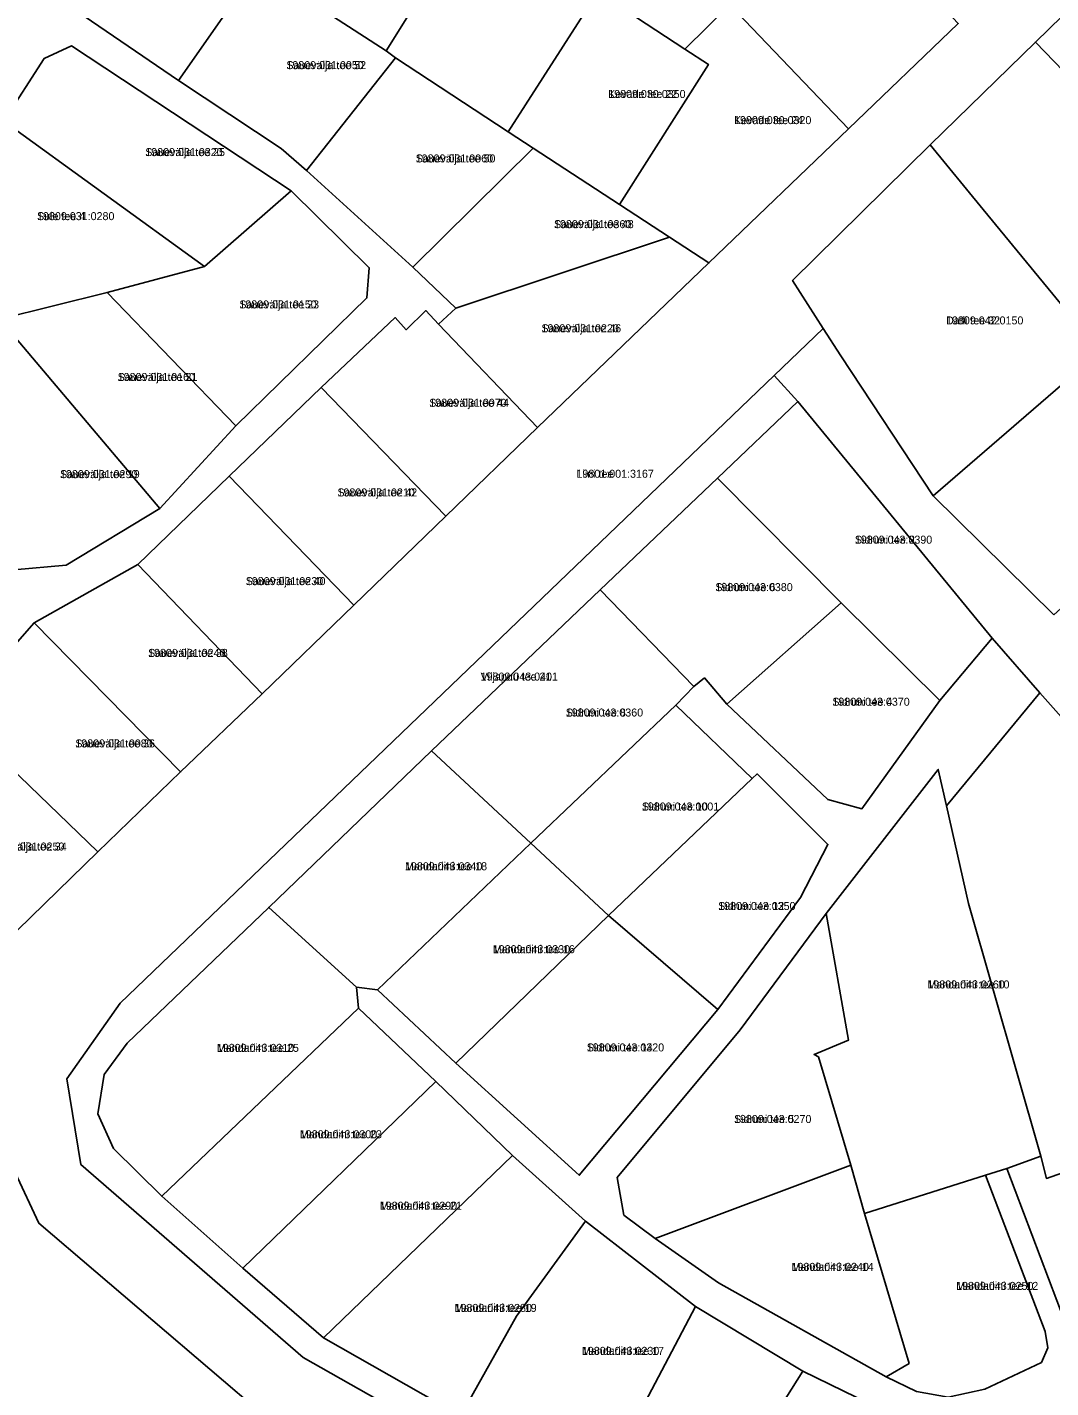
# Model space of a CAD drawing. Extents: x 516875 to 535633, y 6574491 to 6593094.
# Drawn here: x 521809.5 to 522001.4, y 6588394.7 to 6588649.8 of the extents above; entities that cross this region are included whole.
import ezdxf

# ---------------------------------------------------------------- set-up
doc = ezdxf.new("R2010")
doc.units = 0
for name, color, linetype in [('L_AADRESS', 7, 'Continuous'), ('PIIR', 7, 'Continuous'), ('TUNNUS', 7, 'Continuous')]:
    doc.layers.add(name, color=color, linetype=linetype)

msp = doc.modelspace()

# ---------------------------------------------------------------- linework, layer by layer
at = {"layer": 'PIIR'}
for points in [[(521893.2, 6588671.62), (521876.83, 6588645.41), (521853.89, 6588660.25), (521870.17, 6588686.73)], [(521814.85, 6588655.55), (521828.99, 6588676.38), (521833.01, 6588673.97), (521852.62, 6588660.96), (521837.89, 6588639.86)], [(521961.79, 6588674.13), (521984.07, 6588650.49), (521963.51, 6588630.77), (521941.24, 6588653.99)], [(521893.2, 6588671.62), (521916.51, 6588656.43), (521899.69, 6588630.21), (521878.54, 6588644.11), (521876.83, 6588645.41)], [(522009.11, 6588636.07), (521998.56, 6588647.03), (522021.19, 6588669.13), (522031.66, 6588658.42), (522052.99, 6588636.81), (522029.9, 6588614.7)], [(521837.89, 6588639.86), (521852.62, 6588660.96), (521853.89, 6588660.25), (521876.83, 6588645.41), (521878.54, 6588644.11), (521861.88, 6588622.95), (521857.12, 6588627.09)], [(521932.81, 6588645.73), (521937.22, 6588642.84), (521920.56, 6588616.58), (521904.35, 6588627.17), (521899.69, 6588630.21), (521916.51, 6588656.43)], [(521963.51, 6588630.77), (521937.33, 6588605.63), (521929.94, 6588610.46), (521920.56, 6588616.58), (521937.22, 6588642.84), (521932.81, 6588645.73), (521941.24, 6588653.99)], [(521812.66, 6588643.98), (521805.09, 6588632.22), (521787.69, 6588607.6), (521780.83, 6588600.74), (521749.9, 6588570.67), (521765.69, 6588556.88), (521780.6, 6588551.45), (521806.98, 6588548.11), (521816.81, 6588548.97), (521834.35, 6588559.6), (521848.59, 6588575.07), (521873.21, 6588599.07), (521873.65, 6588604.72), (521859, 6588619.13), (521817.82, 6588646.36)], [(521805.09, 6588632.22), (521812.66, 6588643.98), (521817.82, 6588646.36), (521859, 6588619.13), (521842.72, 6588604.96)], [(521998.56, 6588647.03), (522009.11, 6588636.07), (522029.9, 6588614.7), (522007.33, 6588593.08), (521988.73, 6588615.62), (521978.84, 6588627.74)], [(521861.88, 6588622.95), (521878.54, 6588644.11), (521899.69, 6588630.21), (521904.35, 6588627.17), (521881.84, 6588604.83)], [(521787.69, 6588607.6), (521805.09, 6588632.22), (521842.72, 6588604.96), (521824.49, 6588600.1), (521804.33, 6588595.07), (521796.95, 6588599.64)], [(521979.37, 6588561.99), (521962.07, 6588588.22), (521958.77, 6588593.36), (521953.01, 6588602.36), (521978.84, 6588627.74), (521988.73, 6588615.62), (522007.33, 6588593.08), (522010.56, 6588588.92)], [(521929.94, 6588610.46), (521889.89, 6588597.13), (521881.84, 6588604.83), (521904.35, 6588627.17), (521920.56, 6588616.58)], [(521848.59, 6588575.07), (521824.49, 6588600.1), (521842.72, 6588604.96), (521859, 6588619.13), (521873.65, 6588604.72), (521873.21, 6588599.07)], [(521886.61, 6588594.17), (521889.89, 6588597.13), (521929.94, 6588610.46), (521937.33, 6588605.63), (521905.17, 6588574.8)], [(521806.98, 6588548.11), (521796.95, 6588599.64), (521804.33, 6588595.07), (521834.35, 6588559.6), (521816.81, 6588548.97)], [(521834.35, 6588559.6), (521804.33, 6588595.07), (521824.49, 6588600.1), (521848.59, 6588575.07)], [(521864.61, 6588582.26), (521878.47, 6588595.39), (521880.57, 6588593.11), (521884.24, 6588596.68), (521886.61, 6588594.17), (521905.17, 6588574.8), (521887.99, 6588558.13)], [(522002.01, 6588539.62), (521979.37, 6588561.99), (522010.56, 6588588.92), (522030.93, 6588565.87)], [(521847.37, 6588565.64), (521864.61, 6588582.26), (521887.99, 6588558.13), (521870.73, 6588541.45)], [(521954.02, 6588579.63), (521990.44, 6588535.3), (521980.66, 6588523.58), (521962.11, 6588541.89), (521938.95, 6588565.29)], [(521830.26, 6588549.1), (521847.37, 6588565.64), (521870.73, 6588541.45), (521853.54, 6588524.86)], [(521938.95, 6588565.29), (521962.11, 6588541.89), (521940.7, 6588522.89), (521936.47, 6588527.83), (521934.48, 6588526.19), (521916.92, 6588544.33)], [(521838.26, 6588510.21), (521810.8, 6588538.17), (521830.26, 6588549.1), (521853.54, 6588524.86)], [(521885.33, 6588514.16), (521916.92, 6588544.33), (521934.48, 6588526.19), (521931.12, 6588522.68), (521903.95, 6588496.84)], [(521962.11, 6588541.89), (521980.66, 6588523.58), (521966.02, 6588503.3), (521959.6, 6588505.04), (521940.7, 6588522.89)], [(521798.78, 6588524.51), (521810.8, 6588538.17), (521838.26, 6588510.21), (521822.72, 6588495.19), (521804.42, 6588512.93), (521807.19, 6588516.18)], [(521999.54, 6588438.13), (521985.98, 6588485.52), (521981.86, 6588503.81), (521999.35, 6588525.03), (522033.06, 6588487.15), (522077.76, 6588460.57), (522074.08, 6588454.51), (522064.03, 6588443.14), (522041.13, 6588446.11), (522038.02, 6588447.86), (522026.84, 6588443.19), (522000.61, 6588433.97)], [(521931.12, 6588522.68), (521945.44, 6588508.99), (521918.51, 6588483.25), (521903.95, 6588496.84)], [(521780.48, 6588494.46), (521801.87, 6588515.27), (521804.42, 6588512.93), (521822.72, 6588495.19), (521802.64, 6588475.66)], [(521871.22, 6588469.86), (521854.79, 6588484.79), (521885.33, 6588514.16), (521903.95, 6588496.84), (521875.21, 6588469.36)], [(521963.97, 6588436.48), (521957.9, 6588456.75), (521957.06, 6588457.2), (521963.5, 6588459.89), (521959.32, 6588483.62), (521980.32, 6588510.66), (521981.86, 6588503.81), (521985.98, 6588485.52), (521999.54, 6588438.13), (521993.17, 6588435.87), (521989.2, 6588434.61), (521966.52, 6588427.38)], [(521945.44, 6588508.99), (521946.38, 6588509.83), (521959.64, 6588496.61), (521954.53, 6588486.67), (521939.01, 6588465.62), (521918.51, 6588483.25)], [(521875.21, 6588469.36), (521903.95, 6588496.84), (521918.51, 6588483.25), (521889.86, 6588455.59)], [(521825.7, 6588439.58), (521822.75, 6588446.12), (521823.9, 6588453.49), (521828.24, 6588459.32), (521854.79, 6588484.79), (521871.22, 6588469.86), (521871.61, 6588465.87), (521834.74, 6588430.64)], [(521918.51, 6588483.25), (521939.01, 6588465.62), (521913, 6588434.56), (521889.86, 6588455.59)], [(521921.36, 6588427.12), (521920.11, 6588434.15), (521943.18, 6588461.84), (521959.32, 6588483.62), (521963.5, 6588459.89), (521957.06, 6588457.2), (521957.9, 6588456.75), (521963.97, 6588436.48), (521927.24, 6588422.73)], [(521834.74, 6588430.64), (521871.61, 6588465.87), (521886.1, 6588452.14), (521849.95, 6588417.15)], [(521849.95, 6588417.15), (521886.1, 6588452.14), (521900.47, 6588438.26), (521865.08, 6588404.07)], [(522006.15, 6588404.36), (522004.11, 6588406.99), (521993.17, 6588435.87), (521999.54, 6588438.13), (522000.61, 6588433.97), (522026.84, 6588443.19), (522038.04, 6588420.27), (522008.43, 6588404.13)], [(521900.47, 6588438.26), (521914.21, 6588425.95), (521901.23, 6588408.16), (521892.23, 6588392.11), (521892.86, 6588388.28), (521865.08, 6588404.07)], [(521939.12, 6588414.41), (521927.24, 6588422.73), (521963.97, 6588436.48), (521966.52, 6588427.38), (521974.86, 6588399.29), (521970.55, 6588396.81)], [(521767.83, 6588356.93), (521806.88, 6588434.72), (521807.21, 6588435.06), (521811.68, 6588425.58), (521854.43, 6588389.09), (521948.1, 6588337.93), (521923.51, 6588301.46)], [(521976.23, 6588394.06), (521970.55, 6588396.81), (521974.86, 6588399.29), (521966.52, 6588427.38), (521989.2, 6588434.61), (522000.4, 6588405.25), (522000.86, 6588402.21), (521999.67, 6588399.47), (521989.07, 6588394.48), (521982.2, 6588392.97)], [(521892.23, 6588392.11), (521901.23, 6588408.16), (521914.21, 6588425.95), (521934.81, 6588409.94), (521916.48, 6588375.14), (521892.86, 6588388.28)], [(521916.48, 6588375.14), (521934.81, 6588409.94), (521954.92, 6588397.82), (521934.21, 6588364.92)], [(521934.21, 6588364.92), (521954.92, 6588397.82), (521970.07, 6588390.49), (521949.55, 6588356.12)]]:
    msp.add_lwpolyline(points, close=True, dxfattribs=at)
for points in [[(521792.34, 6588670.05), (521814.85, 6588655.55), (521837.89, 6588639.86), (521857.12, 6588627.09), (521861.88, 6588622.95), (521881.84, 6588604.83), (521889.89, 6588597.13), (521886.61, 6588594.17), (521884.24, 6588596.68), (521880.57, 6588593.11), (521878.47, 6588595.39), (521864.61, 6588582.26), (521847.37, 6588565.64), (521830.26, 6588549.1), (521810.8, 6588538.17), (521798.78, 6588524.51)], [(522021.19, 6588669.13), (521998.56, 6588647.03), (521978.84, 6588627.74), (521953.01, 6588602.36), (521958.77, 6588593.36), (521949.58, 6588584.54), (521826.96, 6588466.86), (521816.91, 6588452.64), (521819.57, 6588436.58), (521861.27, 6588400.4), (521906.91, 6588374.55)], [(521941.24, 6588653.99), (521932.81, 6588645.73), (521916.51, 6588656.43)], [(521802.64, 6588475.66), (521822.72, 6588495.19), (521838.26, 6588510.21), (521853.54, 6588524.86), (521870.73, 6588541.45), (521887.99, 6588558.13), (521905.17, 6588574.8), (521937.33, 6588605.63), (521963.51, 6588630.77), (521984.07, 6588650.49)], [(522033.06, 6588487.15), (521999.35, 6588525.03), (521990.44, 6588535.3), (521954.02, 6588579.63), (521949.58, 6588584.54), (521958.77, 6588593.36), (521962.07, 6588588.22), (521979.37, 6588561.99), (522002.01, 6588539.62)], [(521906.91, 6588374.55), (521861.27, 6588400.4), (521819.57, 6588436.58), (521816.91, 6588452.64), (521826.96, 6588466.86), (521949.58, 6588584.54), (521954.02, 6588579.63), (521938.95, 6588565.29), (521916.92, 6588544.33), (521885.33, 6588514.16), (521854.79, 6588484.79), (521828.24, 6588459.32), (521823.9, 6588453.49), (521822.75, 6588446.12), (521825.7, 6588439.58), (521834.74, 6588430.64), (521849.95, 6588417.15), (521865.08, 6588404.07), (521892.86, 6588388.28)], [(521970.07, 6588390.49), (521954.92, 6588397.82), (521934.81, 6588409.94), (521914.21, 6588425.95), (521900.47, 6588438.26), (521886.1, 6588452.14), (521871.61, 6588465.87), (521871.22, 6588469.86), (521875.21, 6588469.36), (521889.86, 6588455.59), (521913, 6588434.56), (521939.01, 6588465.62), (521954.53, 6588486.67), (521959.64, 6588496.61), (521946.38, 6588509.83), (521945.44, 6588508.99), (521931.12, 6588522.68), (521934.48, 6588526.19), (521936.47, 6588527.83), (521940.7, 6588522.89), (521959.6, 6588505.04), (521966.02, 6588503.3), (521980.66, 6588523.58), (521990.44, 6588535.3), (521999.35, 6588525.03), (521981.86, 6588503.81), (521980.32, 6588510.66), (521959.32, 6588483.62), (521943.18, 6588461.84), (521920.11, 6588434.15), (521921.36, 6588427.12), (521927.24, 6588422.73), (521939.12, 6588414.41), (521970.55, 6588396.81), (521976.23, 6588394.06)], [(521854.43, 6588389.09), (521811.68, 6588425.58), (521807.21, 6588435.06)], [(521989.07, 6588394.48), (521999.67, 6588399.47), (522000.86, 6588402.21), (522000.4, 6588405.25), (521989.2, 6588434.61), (521993.17, 6588435.87), (522004.11, 6588406.99), (522006.15, 6588404.36), (522008.43, 6588404.13), (522038.04, 6588420.27), (522052.4, 6588424.89), (522057.35, 6588420.92), (522068.31, 6588414.35), (522094.15, 6588399.29), (522100.45, 6588400.82), (522110.8, 6588415.75), (522120.83, 6588430.51), (522121.82, 6588433.2), (522127.24, 6588429.4), (522110.91, 6588403.64), (522094.05, 6588378.86)]]:
    msp.add_lwpolyline(points, dxfattribs=at)

# ---------------------------------------------------------------- texts
at = {"layer": 'L_AADRESS'}
for s, p in [('Sauevälja tee 52', (521858.1, 6588641.96)), ('Kevade tee 22', (521918.45, 6588636.55)), ('Kevade tee 24', (521942.04, 6588631.65)), ('Sauevälja tee 25', (521831.64, 6588625.66)), ('Sauevälja tee 50', (521882.35, 6588624.47)), ('Sule tee 4', (521811.35, 6588613.65)), ('Sauevälja tee 48', (521908.28, 6588612.15)), ('Sauevälja tee 23', (521849.28, 6588597.1)), ('Datli tee 32', (521981.79, 6588594.1)), ('Sauevälja tee 46', (521905.93, 6588592.63)), ('Sauevälja tee 21', (521826.46, 6588583.49)), ('Sauevälja tee 44', (521884.89, 6588578.66)), ('Sauevälja tee 19', (521815.65, 6588565.28)), ('Liini tee', (521912.5, 6588565.35)), ('Sauevälja tee 42', (521867.68, 6588561.85)), ('Sidruni tee 2', (521964.7, 6588552.99)), ('Sauevälja tee 40', (521850.49, 6588545.22)), ('Sidruni tee 6', (521938.54, 6588544.09)), ('Sauevälja tee 38', (521832.17, 6588531.76)), ('Viljapuu tee 21', (521894.52, 6588527.32)), ('Sidruni tee 4', (521960.48, 6588522.6)), ('Sidruni tee 8', (521910.49, 6588520.58)), ('Sauevälja tee 36', (521818.52, 6588514.79)), ('Sidruni tee 10', (521924.76, 6588502.96)), ('Sauevälja tee 34', (521801.97, 6588495.46)), ('Mandariini tee 18', (521880.34, 6588491.76)), ('Sidruni tee 12', (521939.07, 6588484.31)), ('Mandariini tee 16', (521896.8, 6588476.21)), ('Mandariini tee 10', (521978.3, 6588469.6)), ('Mandariini tee 25', (521845.06, 6588457.71)), ('Sidruni tee 14', (521914.43, 6588457.79)), ('Sidruni tee 5', (521942.04, 6588444.37)), ('Mandariini tee 23', (521860.62, 6588441.51)), ('Mandariini tee 21', (521875.61, 6588428.11)), ('Mandariini tee 14', (521952.82, 6588416.65)), ('Mandariini tee 12', (521983.69, 6588413.08)), ('Mandariini tee 19', (521889.64, 6588408.95)), ('Mandariini tee 17', (521913.52, 6588400.9))]:
    msp.add_text(s, height=1.5, dxfattribs=at).set_placement(p)
at = {"layer": 'TUNNUS'}
for s, p in [('19809:031:0050', (521858.1, 6588641.96)), ('19809:030:0350', (521918.45, 6588636.55)), ('19809:030:0320', (521942.04, 6588631.65)), ('19809:031:0320', (521831.64, 6588625.66)), ('19809:031:0060', (521882.35, 6588624.47)), ('19809:031:0280', (521811.35, 6588613.65)), ('19809:031:0360', (521908.28, 6588612.15)), ('19809:031:0150', (521849.28, 6588597.1)), ('19809:042:0150', (521981.79, 6588594.1)), ('19809:031:0220', (521905.93, 6588592.63)), ('19809:031:0160', (521826.46, 6588583.49)), ('19809:031:0070', (521884.89, 6588578.66)), ('19809:031:0290', (521815.65, 6588565.28)), ('19801:001:3167', (521912.5, 6588565.35)), ('19809:031:0210', (521867.68, 6588561.85)), ('19809:043:0390', (521964.7, 6588552.99)), ('19809:031:0230', (521850.49, 6588545.22)), ('19809:043:0380', (521938.54, 6588544.09)), ('19809:031:0240', (521832.17, 6588531.76)), ('19809:043:0401', (521894.52, 6588527.32)), ('19809:043:0370', (521960.48, 6588522.6)), ('19809:043:0360', (521910.49, 6588520.58)), ('19809:031:0080', (521818.52, 6588514.79)), ('19809:043:0001', (521924.76, 6588502.96)), ('19809:031:0250', (521801.97, 6588495.46)), ('19809:043:0340', (521880.34, 6588491.76)), ('19809:043:0350', (521939.07, 6588484.31)), ('19809:043:0330', (521896.8, 6588476.21)), ('19809:043:0260', (521978.3, 6588469.6)), ('19809:043:0320', (521914.43, 6588457.79)), ('19809:043:0310', (521845.06, 6588457.71)), ('19809:043:0270', (521942.04, 6588444.37)), ('19809:043:0300', (521860.62, 6588441.51)), ('19809:043:0290', (521875.61, 6588428.11)), ('19809:043:0240', (521952.82, 6588416.65)), ('19809:043:0250', (521983.69, 6588413.08)), ('19809:043:0280', (521889.64, 6588408.95)), ('19809:043:0230', (521913.52, 6588400.9))]:
    msp.add_text(s, height=1.5, dxfattribs=at).set_placement(p)

doc.saveas('drawing.dxf')
